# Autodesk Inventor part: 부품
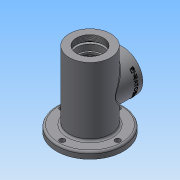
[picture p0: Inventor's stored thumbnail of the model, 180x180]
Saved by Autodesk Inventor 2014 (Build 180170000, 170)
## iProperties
Created: 2016-08
Part Number: 부품
Material: 일반
Document SubType Name: Modeling
Designer: NET
Density: 1 g/cm^3
Appearance: 기본값
Author: NET
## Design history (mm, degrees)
sketch "스케치1"
  geometry: C1 r 31 at (0, 0); 1 further point
  constraints: 1 centre point, 1 coincident
  dimensions: "d0" = 62 diameter of C1
extrude "돌출1" new body sketch "스케치1" stored distance "d1" = 115; taper "d2" = 0 deg
node "작업 평면1"
sketch "스케치2"
  geometry: L1 (31, -57.5)-(31, 57.5) reference; L2 (-31, -57.5)-(-31, 57.5) reference; L3 (-31, -57.5)-(31, -57.5) reference; L4 (31, 57.5)-(-31, 57.5) reference; L5 (0, 57.5)-(0, -57.5); L6 (21, -57.5)-(16.711, -45.491); L7 (13.886, -43.5)-(12.904, -43.5); L8 (12.904, -43.5)-(12.5, -42.8); L9 (12.5, -42.8)-(12.5, -35.8); L10 (12.2, -35.5)-(10, -35.5); L11 (10, -35.5)-(10, -32.8); L12 (10, -32.8)-(13.5, -32.8); L13 (16.5, -29.8)-(16.5, -28.5); L14 (16.5, -28.5)-(17.5, -28.5); L15 (17.5, -28.5)-(17.5, -17.5); L16 (17.5, -17.5)-(23, -17.5); L17 (26, -14.5)-(26, 17.5); L18 (23, 20.5)-(17.5, 20.5); L19 (17.5, 20.5)-(17.5, 31.5); L20 (17.5, 31.5)-(18.5, 31.5); L21 (18.5, 31.5)-(18.5, 33.25); L22 (18.5, 33.25)-(17.5, 33.25); L23 (17.5, 33.25)-(17.5, 36.5); L24 (17.5, 36.5)-(20, 36.5); L25 (20, 36.5)-(20, 45.5); L26 (20, 45.5)-(24, 45.5); L27 (24, 48.5)-(0, 48.5); L28 (24, 48.5)-(24, 45.5); L29 (0, 48.5)-(0, -57.5); L30 (21, -57.5)-(0, -57.5); A1 r 3 centre (13.886, -46.5) between (16.711, -45.491) and (13.886, -43.5); A2 r 3 centre (13.5, -29.8) between (13.5, -32.8) and (16.5, -29.8); A3 r 3 centre (23, -14.5) between (23, -17.5) and (26, -14.5); A4 r 3 centre (23, 17.5) between (26, 17.5) and (23, 20.5); A5 r 0.3 centre (12.2, -35.8) between (12.5, -35.8) and (12.2, -35.5); 7 further points
  constraints: 52 end point, 13 perpendicular, 12 point on line, 10 point on circle, 10 tangent, 8 parallel, 5 centre point, 3 equal radius, 3 midpoint, 2 collinear
  dimensions: "d4" = 42 diameter of L6.start L5; "d5" = 32 diameter of point (16, -43.5) L5; "d6" = 14 vertical distance of L6.start point (16, -43.5); "d7" = 30 deg angle of L9 L8; "d8" = 0.7 vertical distance of L7.end L8.end; "d9" = 7.3 distance of L8.end point (12.5, -35.5); "d10" = 2.7 distance of L10.end L11.end; "d11" = 25 diameter of L9 L5; "d12" = 20 diameter of L11 L5; "d13" = 33 diameter of L13 L5; "d14" = 35 diameter of L15 L5; "d15" = 52 diameter of L17 L5; "d16" = 86 distance between parallel lines of L4 L14; "d17" = 38 distance between parallel lines of L18 L16; "d18" = 3 distance of L27.start L26.end; "d19" = 12 distance between parallel lines of L4 L26; "d20" = 48 diameter of L28 L5; "d21" = 40 diameter of L25 L5; "d23" = 35 diameter of L23 L5; "d24" = 35 diameter of L19 L5; "d25" = 21 distance between parallel lines of L4 L24; "d26" = 37 diameter of L21 L5; "d27" = 1.75 distance of L20.end L21.end; "d28" = 26 distance between parallel lines of L4 L20; "d30" = 56 distance from line of L4 point (26, 1.5); "d32" = 3 radius of A1; "d33" = 0.3 radius of A5
revolve "회전1" sketch "스케치2" stored, may be unused: angle "d31" = 90 deg
hole "구멍1" diameter "d36" = 40.376; stored, may be unused: countersink angle "d40" = 90 deg, drill point angle "d42" = 118 deg; dims "d34" = 10, "d35" = 10, "d37" = 9, "d38" = 4, "d39" = 2, "d41" = 9
sketch "스케치3"
  geometry: L1 (31, 57.5)-(-31, 57.5) reference; C1 r 30 at (0, 1.5); 1 further point
  constraints: 1 centre point, 1 vertical alignment
  dimensions: "d43" = 60 diameter of C1; "d44" = 56 distance from line of L1 C1.centre
extrude "돌출2" join sketch "스케치3" stored distance "d45" = 115; taper "d46" = 0 deg
hole "구멍2" diameter "d49" = 38; stored, may be unused: countersink angle "d53" = 90 deg, drill point angle "d55" = 118 deg; dims "d47" = 10, "d48" = 10, "d50" = 38, "d51" = 4, "d52" = 2, "d54" = 9
chamfer "모따기1" distance "d56" = 1; stored, may be unused: second distance "d57" = 2, angle "d58" = 45 deg
node "작업 평면2"
sketch "스케치4"
  geometry: C1 r 50 at (0, 0); C2 r 31 at (0, 0) reference; C3 r 31 at (0, 0); 1 further point
  constraints: 2 centre point, 2 coincident, 1 concentric
  dimensions: "d60" = 100 diameter of C1
extrude "돌출3" join sketch "스케치4" distance "d61" = 10; taper "d62" = 0 deg
sketch "스케치5"
  geometry: C1 r 31 at (0, 0) reference; C2 r 4 at (0, 41.5)
  constraints: 1 centre point, 1 vertical alignment
  dimensions: "d63" = 8 diameter of C2; "d64" = 41.5 distance of C1.centre C2.centre
extrude "돌출4" cut sketch "스케치5" stored distance "d65" = 10; taper "d66" = 0 deg
fillet "모깎기1" dims "d70" = 3
sketch "스케치6"
  geometry: C1 r 30 at (0, 0) reference; 2 further points
  constraints: 1 horizontal alignment
  dimensions: "d71" = 24 distance of point (-24, 0) C1.centre
hole "구멍3" sketch "스케치6" at (-24, 0) diameter "d72" = 3.242; stored, may be unused: countersink angle "d76" = 90 deg, drill point angle "d78" = 118 deg; dims "d73" = 8, "d74" = 4, "d75" = 2, "d77" = 10
chamfer "모따기2" distance "d82" = 1; stored, may be unused: second distance "d83" = 2, angle "d84" = 45 deg
node "작업 평면3"
sketch "스케치7"
  geometry: L1 (49, 31.5)-(49, -28.5) reference; L2 (31, 57.5)-(-31, 57.5) reference; 2 further points
  constraints: 1 other
  dimensions: "d86" = 10 distance from line of L1 point (39, 1.5); "d87" = 56 distance from line of L2 point (39, 1.5)
feature "엠보싱1" sketch "스케치7" dims "d88" = 0.5, "d89" = 0
node "솔리드1"
pattern_circular "원형 패턴1" dims angle "d68" = 360 deg
pattern_circular "원형 패턴2" dims angle "d80" = 360 deg
other parameters: "d3" = 49, "d59" = -44.5
